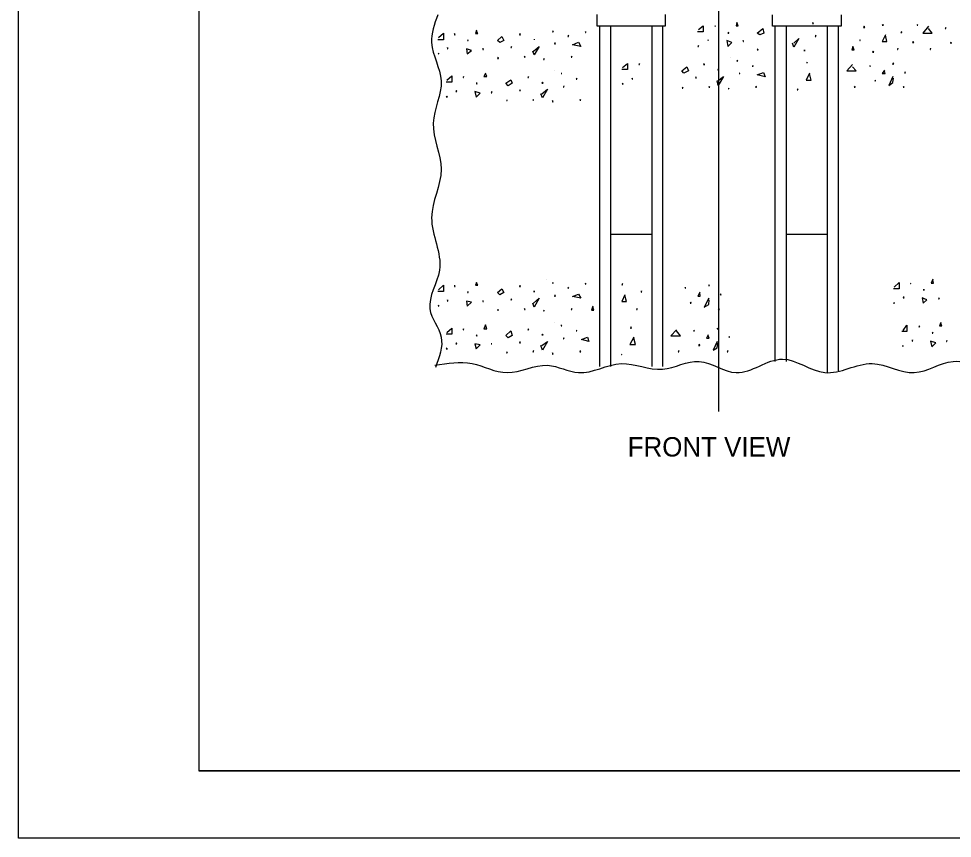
# Model space of a CAD drawing. Extents: x 637580 to 641008, y 294594 to 295782.
# Drawn here: x 637580.3 to 637787.5, y 294593.6 to 294775.6 of the extents above; entities that cross this region are included whole.
import ezdxf

# ---------------------------------------------------------------- set-up
doc = ezdxf.new("R2010")
doc.units = 0
for name, color, linetype in [('1', 7, 'Continuous'), ('2', 7, 'Continuous'), ('PLT-BNDY', 7, 'Continuous')]:
    doc.layers.add(name, color=color, linetype=linetype)

msp = doc.modelspace()

# ---------------------------------------------------------------- linework, layer by layer
at = {"layer": '1'}
for p, q in [((637620.31, 295172.63), (637620.31, 294608.63)), ((638406.31, 294608.63), (637620.31, 294608.63)), ((637620.31, 294608.63), (638206.31, 294608.63))]:
    msp.add_line(p, q, dxfattribs=at)
at = {"layer": '2'}
for p, q in [((637735.69, 294688.38), (637735.69, 294940.5)), ((637708.69, 294773.88), (637708.69, 294776.5)), ((637723.81, 294776.5), (637723.81, 294773.88)), ((637747.56, 294773.88), (637747.56, 294776.38)), ((637762.81, 294776.38), (637762.81, 294773.88)), ((637723.81, 294773.88), (637708.69, 294773.88)), ((637709.31, 294698.38), (637709.31, 294773.88)), ((637711.69, 294698.38), (637711.69, 294773.88)), ((637720.81, 294773.88), (637720.81, 294698.38)), ((637723.19, 294773.88), (637723.19, 294698.38)), ((637762.81, 294773.88), (637747.56, 294773.88)), ((637748.19, 294699.5), (637748.19, 294773.88)), ((637750.69, 294699.5), (637750.69, 294773.88)), ((637759.69, 294773.88), (637759.69, 294697)), ((637762.19, 294773.88), (637762.19, 294697.38)), ((637738.31, 294767), (637738.31, 294767)), ((637699.19, 294764.13), (637699.19, 294764.13)), ((637720.81, 294727.63), (637711.69, 294727.63)), ((637759.69, 294727.63), (637750.69, 294727.63)), ((637697.44, 294717.75), (637697.44, 294717.75)), ((637699.19, 294708.13), (637699.19, 294708.13))]:
    msp.add_line(p, q, dxfattribs=at)
for points in [[(637731.19, 294773.13), (637732.19, 294774), (637732.19, 294772.63), (637730.94, 294772.63)], [(637739.69, 294774.75), (637739.56, 294774), (637739.94, 294774), (637739.69, 294774.75)], [(637756.56, 294774.75), (637756.44, 294774.5), (637756.69, 294774.5), (637756.56, 294774.63)], [(637772.06, 294774.25), (637771.94, 294774.13), (637772.19, 294774.13), (637772.06, 294774.25)], [(637779.69, 294774.25), (637779.69, 294774.13), (637779.81, 294774.13), (637779.69, 294774.25)], [(637673.44, 294771.38), (637674.56, 294772.38), (637674.56, 294770.88), (637673.31, 294770.88)], [(637677.06, 294772.25), (637677.06, 294772), (637677.19, 294772), (637677.06, 294772.25)], [(637681.94, 294773), (637681.69, 294772.25), (637682.19, 294772.25), (637681.94, 294772.88)], [(637691.56, 294772.25), (637691.44, 294772), (637691.69, 294772), (637691.56, 294772.25)], [(637698.94, 294772.88), (637698.81, 294772.63), (637698.94, 294772.63), (637698.94, 294772.88)], [(637702.31, 294771.88), (637702.19, 294771.63), (637702.31, 294771.63), (637702.31, 294771.88)], [(637706.06, 294772.75), (637706.06, 294772.5), (637706.19, 294772.5), (637706.06, 294772.63)], [(637734.94, 294773.88), (637734.81, 294773.88), (637734.94, 294773.88), (637734.94, 294773.88)], [(637737.94, 294772.5), (637737.69, 294772.38), (637737.94, 294772.38), (637737.94, 294772.5)], [(637744.19, 294772.38), (637745.44, 294773.38), (637745.69, 294772.38), (637744.81, 294772), (637744.19, 294772.38)], [(637757.19, 294771.88), (637757.06, 294771.63), (637757.19, 294771.63), (637757.19, 294771.88)], [(637767.94, 294773.88), (637767.81, 294773.63), (637768.06, 294773.63), (637767.94, 294773.88)], [(637772.69, 294772), (637771.94, 294770.5), (637772.94, 294770.5), (637772.69, 294771.88)], [(637776.31, 294772.75), (637776.06, 294772.5), (637776.31, 294772.5), (637776.31, 294772.63)], [(637782.19, 294773.88), (637780.94, 294772.38), (637783.06, 294772.38), (637782.19, 294773.38)], [(637786.06, 294773.63), (637785.94, 294773.38), (637786.06, 294773.38), (637786.06, 294773.63)], [(637680.06, 294770.88), (637679.94, 294770.75), (637680.06, 294770.75), (637680.06, 294770.88)], [(637686.56, 294770.75), (637687.56, 294771.63), (637687.94, 294770.75), (637687.06, 294770.25), (637686.56, 294770.75)], [(637694.69, 294771), (637694.69, 294770.88), (637694.69, 294770.88), (637694.69, 294770.88)], [(637699.31, 294770.25), (637699.19, 294770), (637699.44, 294770), (637699.31, 294770.13)], [(637705.06, 294769.38), (637703.19, 294769.75), (637704.56, 294770.38), (637705.06, 294769.38)], [(637733.31, 294770.88), (637733.31, 294770.75), (637733.31, 294770.75), (637733.31, 294770.88)], [(637737.44, 294770.75), (637737.69, 294769.38), (637738.56, 294770.25), (637737.44, 294770.75)], [(637741.06, 294770.75), (637741.06, 294770.5), (637741.19, 294770.5), (637741.06, 294770.75)], [(637752.31, 294770.13), (637753.44, 294771.13), (637752.31, 294769.25), (637752.06, 294770.13)], [(637767.06, 294770.88), (637766.94, 294770.75), (637767.06, 294770.75), (637767.06, 294770.88)], [(637778.81, 294770.5), (637778.69, 294770.25), (637778.94, 294770.25), (637778.81, 294770.5)], [(637787.19, 294770.38), (637787.06, 294770.13), (637787.31, 294770.13), (637787.19, 294770.25)], [(637673.44, 294767.88), (637673.44, 294767.75), (637673.56, 294767.75), (637673.44, 294767.88)], [(637675.44, 294769.13), (637675.44, 294768.88), (637675.56, 294768.88), (637675.44, 294769.13)], [(637679.69, 294768.88), (637679.81, 294767.75), (637680.81, 294768.5), (637679.69, 294768.88)], [(637683.31, 294769), (637683.31, 294768.75), (637683.44, 294768.75), (637683.31, 294768.88)], [(637689.69, 294769.38), (637689.56, 294769.13), (637689.69, 294769.13), (637689.69, 294769.38)], [(637694.56, 294768.38), (637695.81, 294769.38), (637694.69, 294767.5), (637694.44, 294768.38)], [(637731.19, 294769.63), (637731.06, 294769.38), (637731.19, 294769.38), (637731.19, 294769.63)], [(637744.31, 294768.88), (637744.19, 294768.63), (637744.44, 294768.63), (637744.31, 294768.75)], [(637754.69, 294768.63), (637754.69, 294768.38), (637754.69, 294768.38), (637754.69, 294768.63)], [(637765.44, 294769.38), (637765.19, 294768.63), (637765.69, 294768.63), (637765.44, 294769.38)], [(637769.94, 294768.38), (637769.81, 294768.13), (637770.06, 294768.13), (637769.94, 294768.38)], [(637775.44, 294769), (637775.31, 294768.75), (637775.44, 294768.75), (637775.44, 294768.88)], [(637782.69, 294769), (637782.56, 294768.75), (637782.69, 294768.75), (637782.69, 294768.88)], [(637686.69, 294767), (637686.56, 294766.75), (637686.81, 294766.75), (637686.69, 294767)], [(637692.56, 294767.25), (637692.56, 294767), (637692.69, 294767), (637692.56, 294767.25)], [(637696.94, 294766.75), (637696.81, 294766.5), (637696.94, 294766.5), (637696.94, 294766.75)], [(637703.06, 294767.25), (637702.94, 294767), (637703.06, 294767), (637703.06, 294767.25)], [(637739.81, 294766.38), (637739.69, 294766.13), (637739.81, 294766.13), (637739.81, 294766.38)], [(637755.31, 294765.88), (637755.19, 294765.75), (637755.31, 294765.75), (637755.31, 294765.88)], [(637774.44, 294765.75), (637774.19, 294765.5), (637774.44, 294765.5), (637774.44, 294765.75)], [(637714.31, 294764.75), (637715.44, 294765.63), (637715.44, 294764.25), (637714.19, 294764.25)], [(637718.06, 294765.63), (637717.94, 294765.38), (637718.06, 294765.38), (637718.06, 294765.5)], [(637727.44, 294764), (637728.56, 294764.88), (637728.94, 294764), (637727.94, 294763.5), (637727.44, 294764)], [(637732.44, 294765.63), (637732.31, 294765.38), (637732.56, 294765.38), (637732.44, 294765.5)], [(637735.56, 294764.38), (637735.44, 294764.13), (637735.69, 294764.13), (637735.56, 294764.38)], [(637743.31, 294765.13), (637743.06, 294765), (637743.31, 294765), (637743.31, 294765.13)], [(637745.94, 294762.63), (637744.19, 294763.13), (637745.56, 294763.63), (637745.94, 294762.63)], [(637765.31, 294765.38), (637764.06, 294764), (637766.19, 294764), (637765.31, 294764.88)], [(637769.19, 294765.13), (637769.19, 294765), (637769.31, 294765), (637769.19, 294765.13)], [(637772.44, 294764.13), (637771.94, 294763.38), (637772.56, 294763.38), (637772.44, 294764)], [(637777.06, 294763.75), (637776.94, 294763.5), (637777.06, 294763.5), (637777.06, 294763.75)], [(637675.31, 294761.88), (637676.44, 294762.88), (637676.44, 294761.5), (637675.19, 294761.5)], [(637679.06, 294762.75), (637678.94, 294762.5), (637679.06, 294762.5), (637679.06, 294762.63)], [(637683.94, 294763.5), (637683.56, 294762.75), (637684.19, 294762.75), (637683.94, 294763.38)], [(637688.44, 294761.25), (637689.56, 294762), (637689.81, 294761.25), (637688.94, 294760.63), (637688.44, 294761.25)], [(637693.44, 294762.75), (637693.31, 294762.5), (637693.44, 294762.5), (637693.44, 294762.63)], [(637700.69, 294763.38), (637700.69, 294763.38), (637700.81, 294763.38), (637700.69, 294763.38)], [(637704.19, 294762.38), (637704.06, 294762.13), (637704.19, 294762.13), (637704.19, 294762.38)], [(637716.44, 294762.38), (637716.44, 294762.13), (637716.56, 294762.13), (637716.44, 294762.38)], [(637730.56, 294762.63), (637730.56, 294762.38), (637730.69, 294762.38), (637730.56, 294762.63)], [(637735.44, 294761.75), (637736.69, 294762.75), (637735.56, 294760.75), (637735.31, 294761.75)], [(637740.31, 294763.5), (637740.19, 294763.38), (637740.31, 294763.38), (637740.31, 294763.38)], [(637755.81, 294763.5), (637755.06, 294761.88), (637756.19, 294761.88), (637755.81, 294763.38)], [(637770.44, 294761.88), (637770.31, 294761.75), (637770.44, 294761.75), (637770.44, 294761.88)], [(637774.31, 294762.75), (637773.44, 294760.75), (637774.31, 294761.38), (637774.44, 294762.38)], [(637677.44, 294759.63), (637677.31, 294759.38), (637677.56, 294759.38), (637677.44, 294759.63)], [(637681.94, 294761.38), (637681.94, 294761.13), (637682.06, 294761.13), (637681.94, 294761.25)], [(637691.56, 294759.75), (637691.44, 294759.63), (637691.69, 294759.63), (637691.56, 294759.75)], [(637696.44, 294758.88), (637697.69, 294759.88), (637696.56, 294758), (637696.19, 294758.88)], [(637696.56, 294761.5), (637696.44, 294761.25), (637696.69, 294761.25), (637696.56, 294761.5)], [(637701.31, 294760.63), (637701.19, 294760.38), (637701.31, 294760.38), (637701.31, 294760.5)], [(637714.31, 294761.25), (637714.31, 294761), (637714.44, 294761), (637714.31, 294761.25)], [(637727.69, 294760.38), (637727.56, 294760.13), (637727.69, 294760.13), (637727.69, 294760.38)], [(637733.56, 294760.5), (637733.44, 294760.38), (637733.69, 294760.38), (637733.56, 294760.5)], [(637737.94, 294760.13), (637737.81, 294760), (637737.94, 294760), (637737.94, 294760.13)], [(637744.06, 294760.5), (637743.81, 294760.38), (637744.06, 294760.38), (637744.06, 294760.5)], [(637753.19, 294760), (637753.06, 294759.75), (637753.19, 294759.75), (637753.19, 294760)], [(637765.94, 294760.5), (637765.69, 294760.38), (637765.94, 294760.38), (637765.94, 294760.5)], [(637776.69, 294760.5), (637776.56, 294760.38), (637776.81, 294760.38), (637776.69, 294760.5)], [(637675.31, 294758.38), (637675.19, 294758.25), (637675.44, 294758.25), (637675.31, 294758.38)], [(637681.56, 294759.38), (637681.81, 294758.13), (637682.69, 294759), (637681.56, 294759.38)], [(637685.31, 294759.38), (637685.19, 294759.13), (637685.31, 294759.13), (637685.31, 294759.38)], [(637688.69, 294757.5), (637688.56, 294757.38), (637688.69, 294757.38), (637688.69, 294757.5)], [(637694.56, 294757.63), (637694.44, 294757.5), (637694.56, 294757.5), (637694.56, 294757.63)], [(637698.81, 294757.38), (637698.81, 294757.13), (637698.94, 294757.13), (637698.81, 294757.38)], [(637704.94, 294757.63), (637704.81, 294757.5), (637705.06, 294757.5), (637704.94, 294757.63)], [(637673.44, 294715.38), (637674.56, 294716.38), (637674.56, 294715), (637673.31, 294715)], [(637677.06, 294716.38), (637677.06, 294716.13), (637677.19, 294716.13), (637677.06, 294716.25)], [(637681.94, 294717), (637681.69, 294716.38), (637682.19, 294716.38), (637681.94, 294717)], [(637691.56, 294716.38), (637691.44, 294716.13), (637691.69, 294716.13), (637691.56, 294716.25)], [(637698.94, 294717), (637698.81, 294716.88), (637698.94, 294716.88), (637698.94, 294717)], [(637702.31, 294716), (637702.19, 294715.75), (637702.31, 294715.75), (637702.31, 294715.88)], [(637706.06, 294716.88), (637706.06, 294716.63), (637706.19, 294716.63), (637706.06, 294716.88)], [(637714.31, 294716.75), (637714.19, 294716.5), (637714.31, 294716.5), (637714.31, 294716.63)], [(637728.19, 294716), (637728.19, 294715.75), (637728.31, 294715.75), (637728.19, 294715.88)], [(637733.56, 294716.5), (637733.44, 294716.25), (637733.56, 294716.25), (637733.56, 294716.5)], [(637774.56, 294716), (637775.69, 294717), (637775.69, 294715.63), (637774.44, 294715.63)], [(637778.31, 294716.88), (637778.19, 294716.75), (637778.31, 294716.75), (637778.31, 294716.88)], [(637783.19, 294717.75), (637782.81, 294716.88), (637783.31, 294716.88), (637783.19, 294717.63)], [(637680.06, 294715), (637679.94, 294714.75), (637680.06, 294714.75), (637680.06, 294714.88)], [(637686.56, 294714.75), (637687.56, 294715.63), (637687.94, 294714.75), (637687.06, 294714.25), (637686.56, 294714.75)], [(637694.69, 294715.13), (637694.69, 294714.88), (637694.69, 294714.88), (637694.69, 294715.13)], [(637699.31, 294714.25), (637699.19, 294714), (637699.44, 294714), (637699.31, 294714.13)], [(637705.06, 294713.5), (637703.19, 294713.88), (637704.56, 294714.38), (637705.06, 294713.5)], [(637714.81, 294714.25), (637714.19, 294712.75), (637715.19, 294712.75), (637714.81, 294714.13)], [(637718.56, 294715.13), (637718.44, 294714.88), (637718.56, 294714.88), (637718.56, 294715.13)], [(637731.44, 294714.88), (637731.06, 294714), (637731.56, 294714), (637731.44, 294714.75)], [(637736.06, 294714.5), (637736.06, 294714.25), (637736.19, 294714.25), (637736.06, 294714.5)], [(637776.69, 294713.88), (637776.56, 294713.63), (637776.81, 294713.63), (637776.69, 294713.75)], [(637781.19, 294715.38), (637781.06, 294715.38), (637781.31, 294715.38), (637781.19, 294715.38)], [(637673.44, 294712), (637673.44, 294711.75), (637673.56, 294711.75), (637673.44, 294712)], [(637675.44, 294713.13), (637675.44, 294712.88), (637675.56, 294712.88), (637675.44, 294713.13)], [(637679.69, 294712.88), (637679.81, 294711.75), (637680.81, 294712.63), (637679.69, 294712.88)], [(637683.31, 294713), (637683.31, 294712.75), (637683.44, 294712.75), (637683.31, 294712.88)], [(637689.69, 294713.38), (637689.56, 294713.13), (637689.69, 294713.13), (637689.69, 294713.38)], [(637694.56, 294712.38), (637695.81, 294713.5), (637694.69, 294711.5), (637694.44, 294712.38)], [(637729.44, 294712.63), (637729.31, 294712.38), (637729.56, 294712.38), (637729.44, 294712.63)], [(637733.44, 294713.5), (637732.44, 294711.5), (637733.44, 294712.13), (637733.56, 294713.13)], [(637774.56, 294712.5), (637774.44, 294712.38), (637774.69, 294712.38), (637774.56, 294712.5)], [(637780.81, 294713.63), (637781.06, 294712.38), (637781.81, 294713.13), (637780.81, 294713.63)], [(637784.56, 294713.63), (637784.44, 294713.38), (637784.56, 294713.38), (637784.56, 294713.63)], [(637686.69, 294711), (637686.56, 294710.88), (637686.81, 294710.88), (637686.69, 294711)], [(637692.56, 294711.25), (637692.56, 294711), (637692.69, 294711), (637692.56, 294711.25)], [(637696.94, 294710.88), (637696.81, 294710.75), (637696.94, 294710.75), (637696.94, 294710.88)], [(637703.06, 294711.25), (637702.94, 294711), (637703.06, 294711), (637703.06, 294711.25)], [(637707.69, 294711.75), (637707.44, 294710.88), (637707.94, 294710.88), (637707.69, 294711.63)], [(637717.56, 294711.25), (637717.44, 294711), (637717.56, 294711), (637717.56, 294711.25)], [(637735.69, 294711.25), (637735.56, 294711), (637735.81, 294711), (637735.69, 294711.25)], [(637784.94, 294708.13), (637784.69, 294707.38), (637785.19, 294707.38), (637784.94, 294708)], [(637675.31, 294705.88), (637676.44, 294706.88), (637676.44, 294705.5), (637675.19, 294705.5)], [(637679.06, 294706.75), (637678.94, 294706.5), (637679.06, 294706.5), (637679.06, 294706.75)], [(637683.94, 294707.63), (637683.56, 294706.75), (637684.19, 294706.75), (637683.94, 294707.63)], [(637688.44, 294705.25), (637689.56, 294706.25), (637689.81, 294705.25), (637688.94, 294704.75), (637688.44, 294705.25)], [(637693.44, 294706.75), (637693.31, 294706.5), (637693.44, 294706.5), (637693.44, 294706.75)], [(637700.69, 294707.63), (637700.69, 294707.38), (637700.81, 294707.38), (637700.69, 294707.5)], [(637704.19, 294706.38), (637704.06, 294706.25), (637704.19, 294706.25), (637704.19, 294706.38)], [(637716.19, 294707.13), (637716.06, 294706.88), (637716.31, 294706.88), (637716.19, 294707.13)], [(637726.31, 294706.5), (637725.06, 294705.13), (637727.19, 294705.13), (637726.31, 294706.25)], [(637730.19, 294706.38), (637730.06, 294706.25), (637730.31, 294706.25), (637730.19, 294706.38)], [(637735.31, 294706.88), (637735.31, 294706.75), (637735.44, 294706.75), (637735.31, 294706.88)], [(637776.56, 294706.38), (637777.44, 294707.5), (637777.44, 294706.13), (637776.31, 294706.13)], [(637780.19, 294707.38), (637780.06, 294707.13), (637780.19, 294707.13), (637780.19, 294707.38)], [(637783.19, 294706), (637783.06, 294705.75), (637783.19, 294705.75), (637783.19, 294706)], [(637677.44, 294703.63), (637677.31, 294703.38), (637677.56, 294703.38), (637677.44, 294703.63)], [(637681.94, 294705.38), (637681.94, 294705.13), (637682.06, 294705.13), (637681.94, 294705.38)], [(637691.56, 294703.88), (637691.44, 294703.63), (637691.69, 294703.63), (637691.56, 294703.75)], [(637696.44, 294703), (637697.69, 294703.88), (637696.56, 294702), (637696.19, 294703)], [(637696.56, 294705.5), (637696.44, 294705.38), (637696.69, 294705.38), (637696.56, 294705.5)], [(637701.31, 294704.75), (637701.19, 294704.5), (637701.31, 294704.5), (637701.31, 294704.75)], [(637706.81, 294703.88), (637705.19, 294704.38), (637706.56, 294704.88), (637706.81, 294703.88)], [(637716.81, 294704.88), (637715.94, 294703.25), (637717.19, 294703.25), (637716.81, 294704.63)], [(637733.31, 294705.38), (637732.94, 294704.63), (637733.56, 294704.63), (637733.31, 294705.25)], [(637735.31, 294703.88), (637734.44, 294702), (637735.31, 294702.5), (637735.44, 294703.63)], [(637738.06, 294705), (637737.94, 294704.88), (637738.06, 294704.88), (637738.06, 294705)], [(637778.69, 294704.25), (637778.56, 294704), (637778.69, 294704), (637778.69, 294704.25)], [(637782.69, 294704), (637782.94, 294702.75), (637783.81, 294703.63), (637782.69, 294704)], [(637786.31, 294704.13), (637786.19, 294703.88), (637786.31, 294703.88), (637786.31, 294704)], [(637675.31, 294702.5), (637675.19, 294702.25), (637675.44, 294702.25), (637675.31, 294702.38)], [(637681.56, 294703.38), (637681.81, 294702.25), (637682.69, 294703.13), (637681.56, 294703.38)], [(637685.31, 294703.38), (637685.19, 294703.38), (637685.31, 294703.38), (637685.31, 294703.38)], [(637688.69, 294701.63), (637688.56, 294701.38), (637688.69, 294701.38), (637688.69, 294701.63)], [(637694.56, 294701.88), (637694.44, 294701.63), (637694.56, 294701.63), (637694.56, 294701.75)], [(637704.94, 294701.88), (637704.81, 294701.63), (637705.06, 294701.63), (637704.94, 294701.75)], [(637726.81, 294701.88), (637726.69, 294701.63), (637726.81, 294701.63), (637726.81, 294701.75)], [(637731.44, 294703.25), (637731.19, 294703), (637731.44, 294703), (637731.44, 294703.13)], [(637737.69, 294701.88), (637737.56, 294701.63), (637737.69, 294701.63), (637737.69, 294701.75)], [(637776.56, 294703), (637776.44, 294702.88), (637776.56, 294702.88), (637776.56, 294703)], [(637698.81, 294701.38), (637698.81, 294701.13), (637698.94, 294701.13), (637698.81, 294701.38)], [(637714.19, 294701.13), (637714.06, 294701), (637714.19, 294701), (637714.19, 294701.13)]]:
    msp.add_lwpolyline(points, dxfattribs=at)
for points in [[(637673.31, 294776.38), (637671.94, 294770.25), (637674.06, 294761.75), (637672.31, 294752.38), (637674.06, 294742.13), (637671.94, 294731.38), (637673.69, 294719.75), (637671.56, 294711.13), (637674.06, 294704.88), (637672.81, 294698.13)], [(637672.69, 294698.63), (637680.94, 294699), (637688.69, 294697), (637697.69, 294698.63), (637704.56, 294697), (637714.06, 294699), (637723.19, 294697.75), (637731.31, 294699.5), (637739.56, 294697), (637749.81, 294700), (637759.19, 294697), (637769.69, 294699), (637779.06, 294697), (637787.69, 294699.5), (637793.69, 294698.25)]]:
    msp.add_spline(points, degree=3, dxfattribs=at)
at = {"layer": 'PLT-BNDY'}
msp.add_lwpolyline([(637580.31, 295187.63), (638421.31, 295187.63), (638421.31, 294593.63), (637580.31, 294593.63)], close=True, dxfattribs=at)

# ---------------------------------------------------------------- texts
at = {"layer": '2'}
msp.add_text('FRONT VIEW', height=4.3, dxfattribs=at).set_placement((637715.46, 294678.38))

doc.saveas('drawing.dxf')
